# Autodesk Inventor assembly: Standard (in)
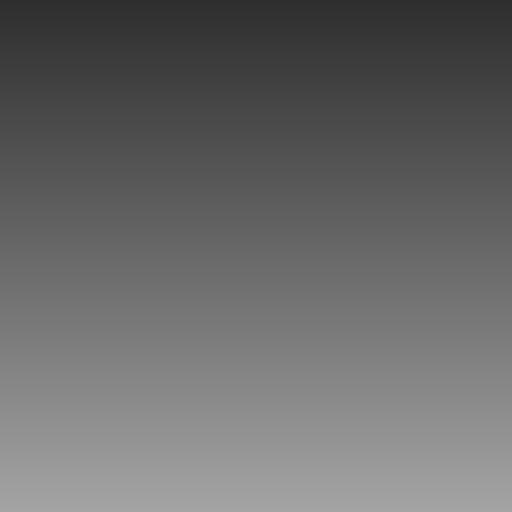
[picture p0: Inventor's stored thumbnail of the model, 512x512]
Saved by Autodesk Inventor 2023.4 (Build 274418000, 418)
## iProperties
Shininess: 64.0
Length Units: 11272
Angle Units: 11279
Time Units: 11290
Mass Units: 11286
Length Display Precision: 3
Angle Display Precision: 2
Compacted: True
Part Number: Standard (in)
Document SubType Name: Assembly
Created: 2002-07
Designer: invbi
Density: 0.0
Volumn: 0.0
Area: 0.0
PropertySet Name: Model Information
Control State: 0
Master: False
Checked Out: False
Author: invbi
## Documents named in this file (1)
- C:\Users\H4ECDSTG\Documents\_VaultWork\Standards\2024 Template Work Group\Templates\Standard (in).iam
